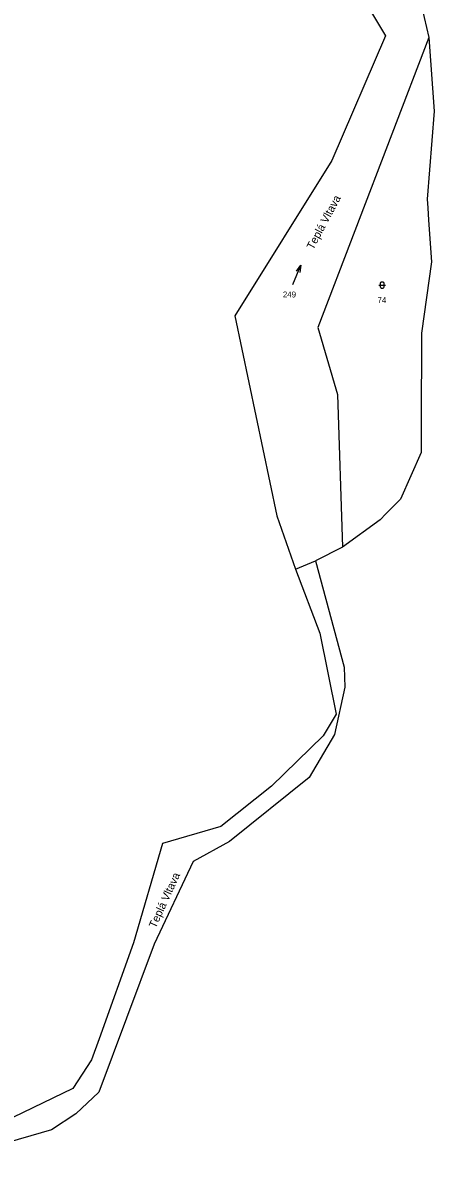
# Model space of a CAD drawing. Extents: x -811039 to -805820, y -1161436 to -1155864.
# Drawn here: x -809634.1 to -809516, y -1161057.7 to -1160727.4 of the extents above; entities that cross this region are included whole.
import ezdxf

# ---------------------------------------------------------------- set-up
doc = ezdxf.new("R2010")
doc.units = 0
for name, color, linetype in [('Default', 7, 'Continuous'), ('Hranice kat_území', 7, 'Continuous'), ('Hranice parcel', 7, 'Continuous'), ('Parcelní čísla', 7, 'Continuous'), ('Pop  PČ popisy', 7, 'Continuous'), ('Značky kultur', 7, 'Continuous')]:
    doc.layers.add(name, color=color, linetype=linetype)

# ---------------------------------------------------------------- blocks, each defined once
blk = doc.blocks.new('316')
at = {"layer": 'Default'}
for points in [[(-1, 1), (0.27, 1), (1, 1)], [(-0.5, 1.5), (-0.4, 1.79), (-0.15, 1.97), (0.16, 1.97), (0.41, 1.79), (0.51, 1.5), (0.51, 0.5), (0.41, 0.21), (0.16, 0.03), (-0.15, 0.03), (-0.4, 0.21), (-0.5, 0.5), (-0.5, 1.5)]]:
    blk.add_lwpolyline(points, dxfattribs=at)
blk = doc.blocks.new('802')
at = {"layer": 'Default'}
blk.add_line((-3, 0), (3, 0), dxfattribs=at)
blk.add_lwpolyline([(1, 0.5), (3, 0), (1, -0.5)], dxfattribs=at)

msp = doc.modelspace()

# ---------------------------------------------------------------- linework, layer by layer
at = {"layer": 'Hranice kat_území'}
for p, q in [((-809524.07, -1160703.76), (-809517.5, -1160731.52)), ((-809517.5, -1160731.52), (-809516.01, -1160752.69)), ((-809516.01, -1160752.69), (-809517.97, -1160777.99)), ((-809517.97, -1160777.99), (-809517.8, -1160780.51)), ((-809517.8, -1160780.51), (-809517.57, -1160784.01)), ((-809517.57, -1160784.01), (-809516.77, -1160796.05)), ((-809516.77, -1160796.05), (-809519.6, -1160816.57)), ((-809519.6, -1160816.57), (-809519.69, -1160842.89)), ((-809519.69, -1160842.89), (-809519.7, -1160850.79)), ((-809519.7, -1160850.79), (-809525.6, -1160864.23)), ((-809525.6, -1160864.23), (-809529.82, -1160868.51)), ((-809531.49, -1160870.2), (-809542.33, -1160878.03)), ((-809529.82, -1160868.51), (-809531.49, -1160870.2)), ((-809542.33, -1160878.03), (-809550.1, -1160881.98)), ((-809550.1, -1160881.98), (-809541.85, -1160912.5)), ((-809541.85, -1160912.5), (-809541.65, -1160918.25)), ((-809541.65, -1160918.25), (-809544.62, -1160931.87)), ((-809544.62, -1160931.87), (-809551.88, -1160944.22)), ((-809551.88, -1160944.22), (-809574.75, -1160962.64)), ((-809574.75, -1160962.64), (-809585.23, -1160968.4)), ((-809585.23, -1160968.4), (-809596.47, -1160992.15)), ((-809596.47, -1160992.15), (-809612.33, -1161034.69)), ((-809612.33, -1161034.69), (-809618.91, -1161040.97)), ((-809618.91, -1161040.97), (-809625.97, -1161045.53)), ((-809625.97, -1161045.53), (-809668.19, -1161057.66))]:
    msp.add_line(p, q, dxfattribs=at)
at = {"layer": 'Hranice parcel'}
for p, q in [((-809567.18, -1160668.94), (-809529.95, -1160731.07)), ((-809517.5, -1160731.52), (-809549.41, -1160814.91)), ((-809529.95, -1160731.07), (-809545.33, -1160766.9)), ((-809545.33, -1160766.9), (-809573.2, -1160811.55)), ((-809573.2, -1160811.55), (-809561.16, -1160869.07)), ((-809549.41, -1160814.91), (-809543.73, -1160834.15)), ((-809543.73, -1160834.15), (-809542.33, -1160878.03)), ((-809561.16, -1160869.07), (-809555.79, -1160884.38)), ((-809555.79, -1160884.38), (-809550.1, -1160881.98)), ((-809555.79, -1160884.38), (-809548.83, -1160902.76)), ((-809548.83, -1160902.76), (-809544.15, -1160926.04)), ((-809544.15, -1160926.04), (-809547.85, -1160932.24)), ((-809547.85, -1160932.24), (-809562.75, -1160946.79)), ((-809562.75, -1160946.79), (-809577.3, -1160958.33)), ((-809577.3, -1160958.33), (-809593.99, -1160963.23)), ((-809593.99, -1160963.23), (-809602.37, -1160991.8)), ((-809602.37, -1160991.8), (-809612.21, -1161019.39)), ((-809612.21, -1161019.39), (-809614.4, -1161025.37)), ((-809614.4, -1161025.37), (-809619.82, -1161033.67)), ((-809619.82, -1161033.67), (-809637.07, -1161042.03))]:
    msp.add_line(p, q, dxfattribs=at)

# ---------------------------------------------------------------- block references
at = {"layer": 'Značky kultur', "rotation": 67.43713199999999}
msp.add_blockref('802', (-809555.44, -1160799.79), dxfattribs=at)
at = {"layer": 'Značky kultur'}
msp.add_blockref('316', (-809530.91, -1160803.7), dxfattribs=at)

# ---------------------------------------------------------------- texts
at = {"layer": 'Parcelní čísla'}
for s, p in [('249', (-809559.45, -1160806.27)), ('74', (-809532.25, -1160807.88))]:
    msp.add_text(s, height=1.7, dxfattribs=at).set_placement(p)
at = {"layer": 'Pop  PČ popisy'}
for rotation, p in [(61.994, (-809550.73, -1160792.72)), (65.546, (-809595.98, -1160987.76))]:
    msp.add_text('Teplá Vltava', height=2.3, rotation=rotation, dxfattribs=at).set_placement(p)

doc.saveas('drawing.dxf')
